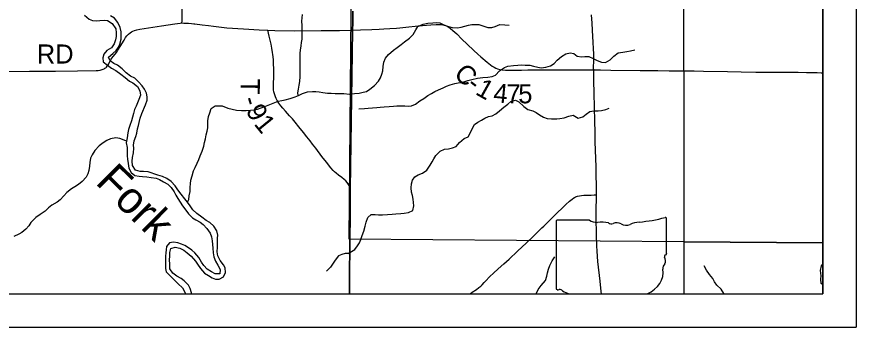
# Model space of a CAD drawing. Extents: x 0 to 34, y 0 to 22.
# Drawn here: x 6.497 to 9, y 14 to 14.926 of the extents above; entities that cross this region are included whole.
import ezdxf

# ---------------------------------------------------------------- set-up
doc = ezdxf.new("R2010")
doc.units = 0
for name, color, linetype in [('Default', 7, 'Continuous'), ('GM_X_County_Road', 7, 'Continuous'), ('GM_X_County_Road_Text', 7, 'Continuous'), ('GM_X_Major_River', 7, 'Continuous'), ('GM_X_Major_River_Text', 7, 'Continuous'), ('GM_X_Minor_River', 7, 'Continuous'), ('GM_X_Section', 7, 'Continuous'), ('GM_X_State_Location', 7, 'Continuous'), ('GM_X_State_Route', 7, 'Continuous'), ('GM_X_Township_Road', 7, 'Continuous'), ('GM_X_Township_Road_Text', 7, 'Continuous'), ('SH_Cut_Line', 7, 'Continuous'), ('SH_Data', 7, 'Continuous')]:
    doc.layers.add(name, color=color, linetype=linetype)

msp = doc.modelspace()

# ---------------------------------------------------------------- linework, layer by layer
at = {"layer": 'Default'}
for p, q in [((8.105, 14.3155), (8.105, 14.1154)), ((8.2048, 14.319), (8.1082, 14.319)), ((8.1444, 14.1), (8.3768, 14.1))]:
    msp.add_line(p, q, dxfattribs=at)
for points in [[(7.4994, 14.9421), (7.4992, 14.9234), (7.4989, 14.9079), (7.4987, 14.8863), (7.4911, 14.4118), (7.4915, 14.4016), (7.4915, 14.3932), (7.4909, 14.3186), (7.4903, 14.275), (7.4902, 14.25), (7.4902, 14.2314), (7.4899, 14.2131), (7.4896, 14.1848), (7.4896, 14.1631), (7.4895, 14.1506), (7.4892, 14.1134), (7.4893, 14.1), (8.9, 14.1), (8.9, 18.2728)], [(3.4093, 14.1), (7.4893, 14.1), (7.4892, 14.1134), (7.4895, 14.1506), (7.4896, 14.1631), (7.4896, 14.1848), (7.4899, 14.2131), (7.4902, 14.2314), (7.4902, 14.25), (7.4903, 14.275), (7.4909, 14.3186), (7.4915, 14.3932), (7.4915, 14.4016), (7.4911, 14.4118), (7.4987, 14.8863), (7.4989, 14.9079), (7.4992, 14.9234), (7.4994, 14.9421)], [(8.4345, 14.2193), (8.4345, 14.2193), (8.4346, 14.2192), (8.4346, 14.3241)]]:
    msp.add_lwpolyline(points, dxfattribs=at)
for points in [[(8.9, 14.2515), (8.9, 15.267), (8.4854, 15.2725), (8.4865, 14.2546)], [(8.4863, 14.1), (8.9, 14.1), (8.9, 14.2515), (8.4865, 14.2546)]]:
    msp.add_lwpolyline(points, close=True, dxfattribs=at)
for centre, major_axis, start_param, end_param in [((8.1088, 14.3159), (0.00382, 0), 1.727492, 3.291633), ((8.2277, 14.3422), (0.037, 0), 4.042888, 4.731792), ((8.3172, 14.5918), (0.3495, 0), 4.814394, 5.042369), ((8.4309, 14.3244), (0.00367, 0), 6.197627, 7.989034), ((8.24, 14.2066), (0.133, 0), 1.404758, 1.657859), ((8.2702, 14.317), (0.0107, 0), 3.836095, 5.185415), ((8.2859, 14.2939), (0.0222, 0), 0.950623, 2.079405), ((8.3146, 14.3256), (0.0267, 0), 4.08156, 5.145723), ((8.3617, 14.2578), (0.0703, 0), 1.699012, 2.107814), ((8.4337, 14.2116), (0.00568, 0), 1.883978, 3.671073), ((8.4307, 14.2188), (0.00393, 0), 5.05454, 6.418171), ((8.3976, 14.1983), (0.0341, 0), 5.934695, 6.695948), ((8.3367, 14.1621), (0.0874, 0), 5.188598, 6.440018), ((8.4477, 14.1754), (0.0248, 0), 2.387724, 3.262537), ((8.1088, 14.115), (0.00385, 0), 2.993084, 4.5083), ((8.1094, 14.1354), (0.0294, 0), 4.665946, 4.897461), ((8.1154, 14.1039), (0.0106, 0), 0.519207, 1.627899), ((8.2492, 14.2837), (0.2524, 0), 4.195997, 4.284306)]:
    msp.add_ellipse(centre, major_axis=major_axis, ratio=0.8, start_param=start_param, end_param=end_param, dxfattribs=at)
at = {"layer": 'GM_X_County_Road'}
for points in [[(7.4989, 14.8857), (7.5218, 14.8869), (7.5559, 14.8879), (7.5775, 14.8888), (7.592, 14.8895), (7.6094, 14.8906), (7.6296, 14.8922), (7.6397, 14.8932), (7.6577, 14.895), (7.6945, 14.8983), (7.7322, 14.9019), (7.7475, 14.9029), (7.7564, 14.903), (7.7624, 14.9025), (7.7681, 14.9018), (7.7719, 14.9009), (7.776, 14.8998), (7.7802, 14.8977), (7.7859, 14.8946), (7.7908, 14.8911), (7.7978, 14.8852), (7.8091, 14.8745), (7.8245, 14.8592), (7.8398, 14.8439), (7.8602, 14.8247), (7.8717, 14.8143), (7.881, 14.8062), (7.9001, 14.7904), (7.9097, 14.7826), (7.9151, 14.7788), (7.9203, 14.7752), (7.9256, 14.7723), (7.9305, 14.7702), (7.9342, 14.7691), (7.9389, 14.7682), (7.9444, 14.7673), (7.9544, 14.767), (7.9661, 14.7667), (7.9841, 14.767), (8.0018, 14.7668), (8.0211, 14.7671), (8.043, 14.7672), (8.0642, 14.7672), (8.0735, 14.7672), (8.1013, 14.7673), (8.1323, 14.7674), (8.154, 14.7674), (8.2005, 14.7676), (8.2173, 14.7676)], [(8.2173, 14.7676), (8.2221, 14.7676), (8.2376, 14.7673), (8.2687, 14.7668), (8.3556, 14.7656), (8.4084, 14.7652), (8.4426, 14.7647), (8.4891, 14.7643), (8.5171, 14.7641), (8.545, 14.7639), (8.6165, 14.7625), (8.6568, 14.7617), (8.7003, 14.761), (8.7376, 14.7608), (8.781, 14.7605), (8.7996, 14.7604), (8.8274, 14.7601), (8.8522, 14.7596), (8.8832, 14.7591), (8.8956, 14.7588), (8.9, 14.7588)]]:
    msp.add_lwpolyline(points, dxfattribs=at)
at = {"layer": 'GM_X_Major_River'}
for points in [[(6.6989, 14.9301), (6.7129, 14.9187), (6.7228, 14.915), (6.736, 14.9134), (6.7455, 14.9142), (6.7588, 14.9153), (6.7683, 14.9142), (6.7819, 14.9055), (6.7925, 14.8899), (6.7936, 14.8774), (6.7936, 14.8672), (6.7921, 14.8573), (6.7879, 14.8448), (6.78, 14.833), (6.7663, 14.8247), (6.7565, 14.8144), (6.7538, 14.8034), (6.7553, 14.7909), (6.7674, 14.7814), (6.7796, 14.7727), (6.7932, 14.7655), (6.8072, 14.7549), (6.8205, 14.7443), (6.8338, 14.734), (6.8432, 14.7284), (6.8569, 14.7174), (6.8641, 14.7048), (6.8663, 14.6919), (6.861, 14.6787), (6.8576, 14.6688), (6.8534, 14.6589), (6.8481, 14.6491), (6.8451, 14.6377), (6.8428, 14.6267), (6.8398, 14.6157), (6.8344, 14.6017), (6.8306, 14.5891), (6.8284, 14.5793), (6.8261, 14.5649), (6.8238, 14.5497), (6.8268, 14.536), (6.8264, 14.5232), (6.8268, 14.511), (6.8279, 14.5015), (6.8291, 14.4883), (6.8317, 14.4738), (6.8382, 14.461), (6.8491, 14.4522), (6.862, 14.4507)], [(6.8757, 14.4644), (6.8651, 14.4644), (6.8518, 14.4685), (6.8423, 14.4818), (6.8416, 14.4951), (6.8423, 14.5057), (6.8454, 14.5197), (6.8465, 14.5338), (6.8458, 14.5433), (6.8469, 14.5558), (6.8519, 14.5687), (6.8549, 14.5789), (6.8576, 14.5918), (6.8602, 14.6013), (6.8625, 14.6108), (6.8652, 14.6237), (6.8705, 14.6369), (6.8811, 14.6627), (6.8857, 14.6768), (6.886, 14.6874), (6.8838, 14.6976), (6.8777, 14.7101), (6.8713, 14.7196), (6.8603, 14.7321), (6.8489, 14.7424), (6.836, 14.7488), (6.8239, 14.7587), (6.8118, 14.7704), (6.7978, 14.7814), (6.7872, 14.786), (6.7762, 14.794), (6.7712, 14.8057), (6.7841, 14.8167), (6.794, 14.8254), (6.8004, 14.8349), (6.805, 14.8444), (6.8084, 14.8588), (6.8088, 14.8691), (6.8084, 14.8804), (6.8054, 14.8941), (6.7986, 14.9085), (6.7891, 14.9218), (6.7766, 14.9286)], [(6.862, 14.4507), (6.8723, 14.4496), (6.8855, 14.4481), (6.8984, 14.4469), (6.9132, 14.4443), (6.9227, 14.4409), (6.9348, 14.434), (6.9481, 14.4261), (6.9579, 14.417), (6.9666, 14.4033), (6.9716, 14.3935), (6.978, 14.384), (6.9844, 14.3726), (6.9916, 14.3623), (7.0011, 14.3487), (7.0098, 14.3377), (7.0216, 14.3259), (7.0314, 14.3199), (7.0439, 14.313), (7.0534, 14.3066), (7.0644, 14.2945), (7.0742, 14.2801), (7.078, 14.2698), (7.0803, 14.2577), (7.0814, 14.2467), (7.0822, 14.2353), (7.0829, 14.222), (7.0848, 14.2099), (7.0897, 14.1966), (7.0973, 14.1849), (7.1037, 14.1716), (7.1026, 14.1587), (7.0893, 14.1594), (7.0776, 14.1647), (7.0655, 14.1727), (7.0548, 14.1845), (7.0484, 14.1943), (7.0405, 14.208), (7.0287, 14.2216), (7.0192, 14.23), (7.0098, 14.2364), (6.9988, 14.2433), (6.9885, 14.2474), (6.9779, 14.2512), (6.965, 14.2535), (6.9529, 14.2516), (6.9442, 14.2402), (6.9427, 14.2307), (6.9419, 14.2213), (6.9411, 14.2118), (6.9404, 14.2008), (6.9404, 14.186), (6.9407, 14.1754), (6.9426, 14.1655), (6.9688, 14.1393), (6.9782, 14.1295), (6.9919, 14.117), (6.9979, 14.1067), (7.0002, 14.1)], [(7.0185, 14.1), (7.018, 14.1029), (7.0146, 14.1151), (7.0093, 14.1253), (6.9968, 14.1382), (6.9873, 14.145), (6.9748, 14.1518), (6.9627, 14.1609), (6.954, 14.1738), (6.9533, 14.1875), (6.9529, 14.2011), (6.9533, 14.2118), (6.9533, 14.2224), (6.9567, 14.2345), (6.9696, 14.2391), (6.9832, 14.236), (6.9957, 14.2296), (7.0052, 14.2216), (7.0173, 14.2114), (7.0298, 14.1974), (7.0359, 14.1879), (7.045, 14.1746), (7.0567, 14.1613), (7.0689, 14.1538), (7.0798, 14.1469), (7.0897, 14.1431), (7.1007, 14.1435), (7.1136, 14.15), (7.12, 14.1636), (7.1189, 14.1769), (7.114, 14.1864), (7.1041, 14.1993), (7.0966, 14.2125), (7.0951, 14.2251), (7.0954, 14.2391), (7.0958, 14.2524), (7.0962, 14.2653), (7.0966, 14.2747), (7.0943, 14.2873), (7.0845, 14.3017), (7.0727, 14.3123), (7.0617, 14.3187), (7.0489, 14.3286), (7.0345, 14.3388), (7.0223, 14.3502), (7.0148, 14.362), (7.0068, 14.3726), (6.9981, 14.3825), (6.9871, 14.3972), (6.978, 14.4098), (6.9693, 14.4219), (6.9576, 14.4344), (6.9447, 14.4435), (6.9314, 14.4496), (6.9181, 14.4538), (6.8893, 14.4629), (6.8757, 14.4644)]]:
    msp.add_lwpolyline(points, dxfattribs=at)
at = {"layer": 'GM_X_Minor_River'}
for points in [[(7.3367, 14.6909), (7.3349, 14.6988), (7.3372, 14.7098), (7.3391, 14.722), (7.341, 14.733), (7.3421, 14.7477), (7.3421, 14.7572), (7.3425, 14.7713), (7.3421, 14.7819), (7.3418, 14.7933), (7.3418, 14.8046), (7.3425, 14.8168), (7.3433, 14.8266), (7.3448, 14.8395), (7.3467, 14.849), (7.3479, 14.8585), (7.3486, 14.8725), (7.3486, 14.8873), (7.3479, 14.8998), (7.3475, 14.9127), (7.3494, 14.9328)], [(7.489, 14.6954), (7.489, 14.6951), (7.504, 14.6965), (7.518, 14.6984), (7.5301, 14.7006), (7.5398, 14.7034), (7.5503, 14.7094), (7.5641, 14.7207), (7.5763, 14.7335), (7.5821, 14.7435), (7.586, 14.7546), (7.5884, 14.7646), (7.5893, 14.7775), (7.592, 14.7908), (7.5963, 14.8027), (7.6055, 14.8132), (7.6204, 14.8257), (7.6312, 14.8339), (7.6431, 14.8433), (7.6531, 14.8511), (7.668, 14.8617), (7.6788, 14.8726), (7.6868, 14.8868), (7.6934, 14.8965), (7.7087, 14.904), (7.7231, 14.9066), (7.7378, 14.9078), (7.7477, 14.9084), (7.7583, 14.9075), (7.7709, 14.9017), (7.7816, 14.8974), (7.7954, 14.8939), (7.8117, 14.8928), (7.8219, 14.8946), (7.8328, 14.8975), (7.8441, 14.9008), (7.8543, 14.9029), (7.8652, 14.9032), (7.8747, 14.9023), (7.8896, 14.8977), (7.9018, 14.8938), (7.9136, 14.8937), (7.9241, 14.8966), (7.9372, 14.903), (7.9528, 14.9022), (7.9649, 14.9006)], [(7.5172, 14.6517), (7.5338, 14.6525), (7.5452, 14.6531), (7.558, 14.6542), (7.5709, 14.6556), (7.5811, 14.6562), (7.5924, 14.6573), (7.6076, 14.6584), (7.6201, 14.6594), (7.6303, 14.6604), (7.6447, 14.6604), (7.6541, 14.6599), (7.6644, 14.6594), (7.6746, 14.6604), (7.6859, 14.6648), (7.6993, 14.6746), (7.7109, 14.6817), (7.7224, 14.6911), (7.734, 14.6974), (7.7441, 14.7034), (7.7546, 14.7078), (7.7688, 14.7142), (7.779, 14.719), (7.7895, 14.7223), (7.803, 14.7264), (7.8132, 14.7285), (7.8268, 14.7308), (7.8422, 14.7353), (7.8543, 14.739), (7.8712, 14.7428), (7.8867, 14.7443), (7.9022, 14.7458), (7.9151, 14.748), (7.9248, 14.7517), (7.937, 14.7641), (7.9516, 14.7747), (7.9617, 14.778), (7.978, 14.7803), (7.9908, 14.781), (8.0026, 14.782), (8.0132, 14.7819), (8.0265, 14.781), (8.0379, 14.7787), (8.0512, 14.7752), (8.0611, 14.7731), (8.0751, 14.775), (8.089, 14.7799), (8.0991, 14.7866), (8.1083, 14.7963), (8.1213, 14.8076), (8.1348, 14.8155), (8.1476, 14.8181), (8.1579, 14.8164), (8.1679, 14.8083), (8.1812, 14.8063), (8.191, 14.8073), (8.2028, 14.8076), (8.2154, 14.8011), (8.2277, 14.7949), (8.2407, 14.7907), (8.2521, 14.7898), (8.2663, 14.797), (8.277, 14.8079), (8.2905, 14.818), (8.304, 14.8206), (8.3165, 14.8221), (8.3271, 14.8238), (8.3399, 14.8268)], [(7.0063, 14.3732), (7.0102, 14.3809), (7.0117, 14.3916), (7.014, 14.4048), (7.0148, 14.4173), (7.0156, 14.4272), (7.0167, 14.4382), (7.0205, 14.4515), (7.0243, 14.4659), (7.0296, 14.4765), (7.0353, 14.4887), (7.0402, 14.5), (7.044, 14.5107), (7.0501, 14.5247), (7.055, 14.5399), (7.0573, 14.5505), (7.0596, 14.5622), (7.0623, 14.574), (7.0649, 14.5846), (7.0668, 14.5945), (7.0668, 14.6153), (7.0691, 14.6282), (7.0729, 14.6392), (7.0771, 14.6518), (7.0892, 14.6605), (7.1002, 14.6605), (7.1101, 14.6597), (7.1268, 14.6537), (7.1396, 14.6499), (7.1529, 14.6472), (7.1669, 14.6465), (7.1813, 14.6465), (7.1946, 14.6472), (7.2045, 14.648), (7.2155, 14.6503), (7.2257, 14.6544), (7.2367, 14.6586), (7.2469, 14.6624), (7.2621, 14.6685), (7.2765, 14.6738), (7.2875, 14.6764), (7.2977, 14.6776), (7.3121, 14.6817), (7.3273, 14.6874), (7.3375, 14.6912), (7.3493, 14.6965), (7.3637, 14.7022), (7.3793, 14.7034), (7.3887, 14.703), (7.399, 14.7015), (7.4103, 14.6996), (7.424, 14.6984), (7.435, 14.6977), (7.4467, 14.6973), (7.4589, 14.6969), (7.4725, 14.6966), (7.489, 14.6951)], [(7.4856, 14.2202), (7.4952, 14.2262), (7.505, 14.2313), (7.513, 14.2425), (7.5192, 14.2521), (7.5232, 14.2617), (7.5275, 14.2736), (7.5317, 14.2862), (7.5359, 14.3011), (7.5394, 14.3137), (7.5444, 14.3267), (7.5541, 14.3361), (7.5662, 14.336), (7.5761, 14.3347), (7.5882, 14.335), (7.6026, 14.3361), (7.6165, 14.3372), (7.6279, 14.3378), (7.6427, 14.3389), (7.6525, 14.3399), (7.6653, 14.3418), (7.6784, 14.3478), (7.6812, 14.3615), (7.6802, 14.3721), (7.6788, 14.3819), (7.677, 14.3925), (7.6745, 14.4027), (7.6731, 14.4152), (7.6743, 14.4277), (7.6771, 14.438), (7.6841, 14.4488), (7.6938, 14.4544), (7.7073, 14.4592), (7.7196, 14.4683), (7.7299, 14.4829), (7.7357, 14.4929), (7.7412, 14.5026), (7.747, 14.5122), (7.7592, 14.5246), (7.7723, 14.5306), (7.7841, 14.532), (7.7969, 14.535), (7.807, 14.5387), (7.8173, 14.551), (7.8315, 14.5624), (7.8427, 14.568), (7.8511, 14.5822), (7.8547, 14.5918), (7.8619, 14.6048), (7.872, 14.6115), (7.8832, 14.6175), (7.8929, 14.6234), (7.9042, 14.6279), (7.9151, 14.6304), (7.9256, 14.6367), (7.9368, 14.6457), (7.949, 14.6562), (7.9609, 14.6656), (7.9706, 14.6727), (7.9842, 14.6768), (7.9945, 14.6717), (8.0088, 14.6584), (8.0212, 14.6496), (8.0357, 14.6454), (8.0456, 14.6407), (8.056, 14.6334), (8.0679, 14.6261), (8.0783, 14.6225), (8.0912, 14.6213), (8.1071, 14.6209), (8.1169, 14.6223), (8.1297, 14.6245), (8.1433, 14.6294), (8.1565, 14.6323), (8.1707, 14.6236), (8.185, 14.6273), (8.1954, 14.6352), (8.2055, 14.6437), (8.2175, 14.6452), (8.2304, 14.6455), (8.2403, 14.6465), (8.2538, 14.6491), (8.2636, 14.6535)], [(6.8245, 14.5544), (6.8177, 14.5577), (6.8048, 14.563), (6.7923, 14.5649), (6.7772, 14.5622), (6.7658, 14.5569), (6.7548, 14.5497), (6.7434, 14.541), (6.7305, 14.5269), (6.7218, 14.514), (6.7176, 14.5038), (6.715, 14.4913), (6.7142, 14.4799), (6.7127, 14.467), (6.7096, 14.4571), (6.7039, 14.4473), (6.6922, 14.4348), (6.6816, 14.426), (6.6706, 14.4188), (6.6607, 14.4124), (6.6467, 14.4014), (6.638, 14.3919), (6.627, 14.3798), (6.6175, 14.3729), (6.6023, 14.3635), (6.5924, 14.3559), (6.5818, 14.3464), (6.5674, 14.3361), (6.5538, 14.327), (6.5397, 14.3122), (6.5329, 14.3024), (6.5249, 14.2925), (6.5128, 14.2827), (6.5033, 14.2773), (6.4885, 14.2705)], [(7.4856, 14.2202), (7.4764, 14.2198), (7.4669, 14.2167), (7.4567, 14.2126), (7.4468, 14.2001), (7.4408, 14.1906), (7.4324, 14.1788), (7.4203, 14.1674)], [(8.0455, 14.1), (8.0515, 14.1122), (8.0606, 14.1246), (8.0739, 14.139), (8.0774, 14.1523), (8.0799, 14.1619), (8.083, 14.1729), (8.0869, 14.1844), (8.0938, 14.1975), (8.1015, 14.2094)], [(8.606, 14.1), (8.6057, 14.1007), (8.5978, 14.1138), (8.5846, 14.1257), (8.578, 14.1354), (8.5724, 14.1451), (8.5627, 14.157), (8.5533, 14.1705), (8.5465, 14.1832)], [(8.9, 14.1268), (8.8956, 14.13), (8.8946, 14.1433), (8.8955, 14.1532), (8.894, 14.1691), (8.8963, 14.1828), (8.9, 14.1879)]]:
    msp.add_lwpolyline(points, dxfattribs=at)
at = {"layer": 'GM_X_Section'}
msp.add_lwpolyline([(7.4976, 15.2767), (8.4854, 15.2725), (8.4865, 14.2546), (7.4886, 14.263)], close=True, dxfattribs=at)
at = {"layer": 'GM_X_State_Route'}
msp.add_lwpolyline([(8.2408, 14.1), (8.24, 14.1064), (8.2363, 14.1372), (8.2299, 14.1959), (8.2274, 14.2268), (8.2265, 14.2423), (8.2257, 14.2765), (8.2251, 14.3262), (8.225, 14.3479), (8.2254, 14.3883), (8.2255, 14.3949), (8.2256, 14.407), (8.2255, 14.4287), (8.225, 14.4474), (8.2244, 14.466), (8.2245, 14.4721), (8.2243, 14.4784), (8.2222, 14.5528), (8.2217, 14.5746), (8.2205, 14.6212), (8.2197, 14.6491), (8.2194, 14.6646), (8.2187, 14.6895), (8.2175, 14.7423), (8.2175, 14.7578), (8.2173, 14.7676), (8.2172, 14.7702), (8.2172, 14.7764), (8.2178, 14.7919), (8.2177, 14.8012), (8.2174, 14.8167), (8.2171, 14.8291), (8.2161, 14.8509), (8.2151, 14.8664), (8.2125, 14.9066), (8.2111, 14.9314)], dxfattribs=at)
at = {"layer": 'GM_X_Township_Road'}
for points in [[(6.9899, 14.9073), (6.9901, 14.9123), (6.9904, 14.9215), (6.9907, 14.9557)], [(7.4989, 14.8857), (7.4991, 14.9074), (7.4994, 14.9229), (7.4996, 14.9415)], [(6.458, 14.763), (6.5356, 14.7635), (6.6132, 14.7635), (6.6783, 14.7642), (6.7341, 14.7654), (6.7403, 14.7657), (6.7464, 14.7665), (6.7493, 14.7672), (6.7522, 14.7681), (6.7551, 14.7691), (6.7578, 14.7704), (6.7604, 14.772), (6.7627, 14.7738), (6.7649, 14.7759), (6.7668, 14.7782), (6.7685, 14.7806), (6.7716, 14.7859), (6.776, 14.7948), (6.7775, 14.797), (6.7789, 14.7998), (6.781, 14.8024), (6.7945, 14.8194), (6.7991, 14.8265), (6.8058, 14.837), (6.8172, 14.8562), (6.8219, 14.8637), (6.826, 14.8692), (6.8307, 14.8738), (6.8357, 14.8776), (6.8397, 14.8806), (6.8434, 14.8827), (6.8485, 14.885), (6.855, 14.8867), (6.8646, 14.8888), (6.9293, 14.8988), (6.969, 14.9047), (6.9847, 14.9068), (6.9899, 14.9073)], [(6.9899, 14.9073), (6.9952, 14.9071), (7.0096, 14.9065), (7.0186, 14.9055), (7.0251, 14.9048), (7.0283, 14.9045), (7.0498, 14.9017), (7.0687, 14.8993), (7.0839, 14.8975), (7.1239, 14.8928), (7.1734, 14.8893), (7.2198, 14.8869), (7.2455, 14.886)], [(7.2455, 14.886), (7.2666, 14.8851), (7.3249, 14.8841), (7.4044, 14.8844), (7.4595, 14.8851), (7.4989, 14.8857)], [(7.4913, 14.4112), (7.4884, 14.4228), (7.4864, 14.4258), (7.4822, 14.4315), (7.4782, 14.4362), (7.4737, 14.4404), (7.4665, 14.4461), (7.4565, 14.4535), (7.4492, 14.4593), (7.4446, 14.4634), (7.4402, 14.4678), (7.434, 14.4748), (7.4204, 14.4917), (7.4072, 14.5089), (7.3886, 14.5337), (7.3792, 14.546), (7.3716, 14.5558), (7.3621, 14.5681), (7.3525, 14.5803), (7.3388, 14.5971), (7.3271, 14.6116), (7.3191, 14.6211), (7.3108, 14.6303), (7.2983, 14.644), (7.2902, 14.6534), (7.2844, 14.6606), (7.279, 14.6682), (7.2741, 14.6761), (7.2712, 14.6816), (7.2686, 14.6873), (7.2664, 14.6931), (7.2646, 14.699), (7.2639, 14.702), (7.2632, 14.7081), (7.263, 14.7175), (7.264, 14.7547), (7.2638, 14.7703), (7.2632, 14.7858), (7.2624, 14.7981), (7.261, 14.8135), (7.2602, 14.8196), (7.2583, 14.8319), (7.256, 14.8441), (7.2532, 14.8562), (7.25, 14.8682), (7.2455, 14.886)], [(7.4895, 14.1), (7.4894, 14.1129), (7.4897, 14.1501), (7.4898, 14.1625), (7.4898, 14.1843), (7.4901, 14.2126), (7.4904, 14.2308), (7.4904, 14.2494), (7.4905, 14.2745), (7.4911, 14.318), (7.4917, 14.3927), (7.4918, 14.401), (7.4913, 14.4112)], [(7.8486, 14.1), (7.8549, 14.1041), (7.868, 14.1126), (7.8754, 14.118), (7.8805, 14.1223), (7.8848, 14.1266), (7.8908, 14.1332), (7.8948, 14.1376), (7.9078, 14.1508), (7.9191, 14.1615), (7.9329, 14.1741), (7.949, 14.1887), (7.9649, 14.2032), (7.9902, 14.2265), (8.0173, 14.2513), (8.037, 14.2709), (8.0479, 14.2819), (8.0569, 14.2904), (8.0627, 14.296), (8.0683, 14.3015), (8.0752, 14.3082), (8.0809, 14.3137), (8.0853, 14.3179), (8.0876, 14.3201), (8.0985, 14.3311), (8.1341, 14.3658), (8.1455, 14.3763), (8.1528, 14.3821), (8.1579, 14.3856), (8.1606, 14.3871), (8.1635, 14.3884), (8.1693, 14.3906), (8.1753, 14.392), (8.1815, 14.3929), (8.1877, 14.3933), (8.2095, 14.3941), (8.2188, 14.3945), (8.2255, 14.3949)]]:
    msp.add_lwpolyline(points, dxfattribs=at)
at = {"layer": 'SH_Cut_Line'}
for points in [[(7.4994, 14.9421), (7.4992, 14.9234), (7.4989, 14.9079), (7.4987, 14.8863), (7.4911, 14.4118), (7.4915, 14.4016), (7.4915, 14.3932), (7.4909, 14.3186), (7.4903, 14.275), (7.4902, 14.25), (7.4902, 14.2314), (7.4899, 14.2131), (7.4896, 14.1848), (7.4896, 14.1631), (7.4895, 14.1506), (7.4892, 14.1134), (7.4893, 14.1), (8.9, 14.1), (8.9, 20.9)], [(2.1, 14.1), (7.4893, 14.1), (7.4892, 14.1134), (7.4895, 14.1506), (7.4896, 14.1631), (7.4896, 14.1848), (7.4899, 14.2131), (7.4902, 14.2314), (7.4902, 14.25), (7.4903, 14.275), (7.4909, 14.3186), (7.4915, 14.3932), (7.4915, 14.4016), (7.4911, 14.4118), (7.4987, 14.8863), (7.4989, 14.9079), (7.4992, 14.9234), (7.4994, 14.9421)]]:
    msp.add_lwpolyline(points, dxfattribs=at)
at = {"layer": 'SH_Data'}
for p, q in [((9, 21), (9, 14)), ((8.9, 20.9), (8.9, 14.1)), ((2.1, 14.1), (8.9, 14.1)), ((2, 14), (9, 14))]:
    msp.add_line(p, q, dxfattribs=at)

# ---------------------------------------------------------------- texts
at = {"layer": 'GM_X_County_Road_Text'}
for s, rotation, p in [('C', 317.609, (7.7974, 14.7503)), ('-', 321.7377, (7.8353, 14.716)), ('1', 330.8417, (7.8618, 14.696)), ('4', 354.3801, (7.9165, 14.6714)), ('7', 0.0545, (7.9575, 14.6677)), ('5', 359.9636, (7.9925, 14.6677))]:
    msp.add_text(s, height=0.0568, rotation=rotation, dxfattribs=at).set_placement(p)
at = {"layer": 'GM_X_Major_River_Text'}
msp.add_text('Fork', height=0.09473, rotation=315.223, dxfattribs=at).set_placement((6.7291, 14.4295))
at = {"layer": 'GM_X_State_Location'}
for s in ['s', 'r']:
    msp.add_text(s, height=0.000189, dxfattribs=at).set_placement((8.2661, 14.2022))
msp.add_text('603', height=0.000189, rotation=0, dxfattribs=at).set_placement((8.1992, 14.1884))
at = {"layer": 'GM_X_Township_Road_Text'}
for s, height, rotation, p in [('RD', 0.05682, 359.9982, (6.557, 14.7863)), ('T', 0.0568, 269.67, (7.1654, 14.7408)), ('9', 0.0568, 298.1329, (7.1792, 14.6464)), ('-', 0.0568, 286.8305, (7.1678, 14.68)), ('1', 0.0568, 309.208, (7.2024, 14.6056))]:
    msp.add_text(s, height=height, rotation=rotation, dxfattribs=at).set_placement(p)

doc.saveas('drawing.dxf')
